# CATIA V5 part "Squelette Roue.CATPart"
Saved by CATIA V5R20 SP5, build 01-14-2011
Part number: Squelette Roue
Bounding box of the stored display mesh (mm): x -160 to -160, y -325 to -325, z -30 to 30
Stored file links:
  U:\CFAO\Thinkmotion\Squelette Roue.CATPart
  U:\CFAO\Thinkmotion\Bras Articule.CATProduct
  U:\CFAO\Thinkmotion\Squelette general.CATPart
  H:\Thinkmotion le vrai\Porte roue.CATPart
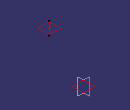
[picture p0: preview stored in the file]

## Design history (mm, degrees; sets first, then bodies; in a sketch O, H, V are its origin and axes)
Set1
  Line1: type Normal, RefPoint Point1, RefSkin Plane2, Start -30, End 30
  Plane1: type OffsetPt, RefPlane xy-plane, RefPoint Point2
Set2
  Plane2: linked copy from another document
  Point1: linked copy from another document
  Point2: linked copy from another document
Body1 (main body)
